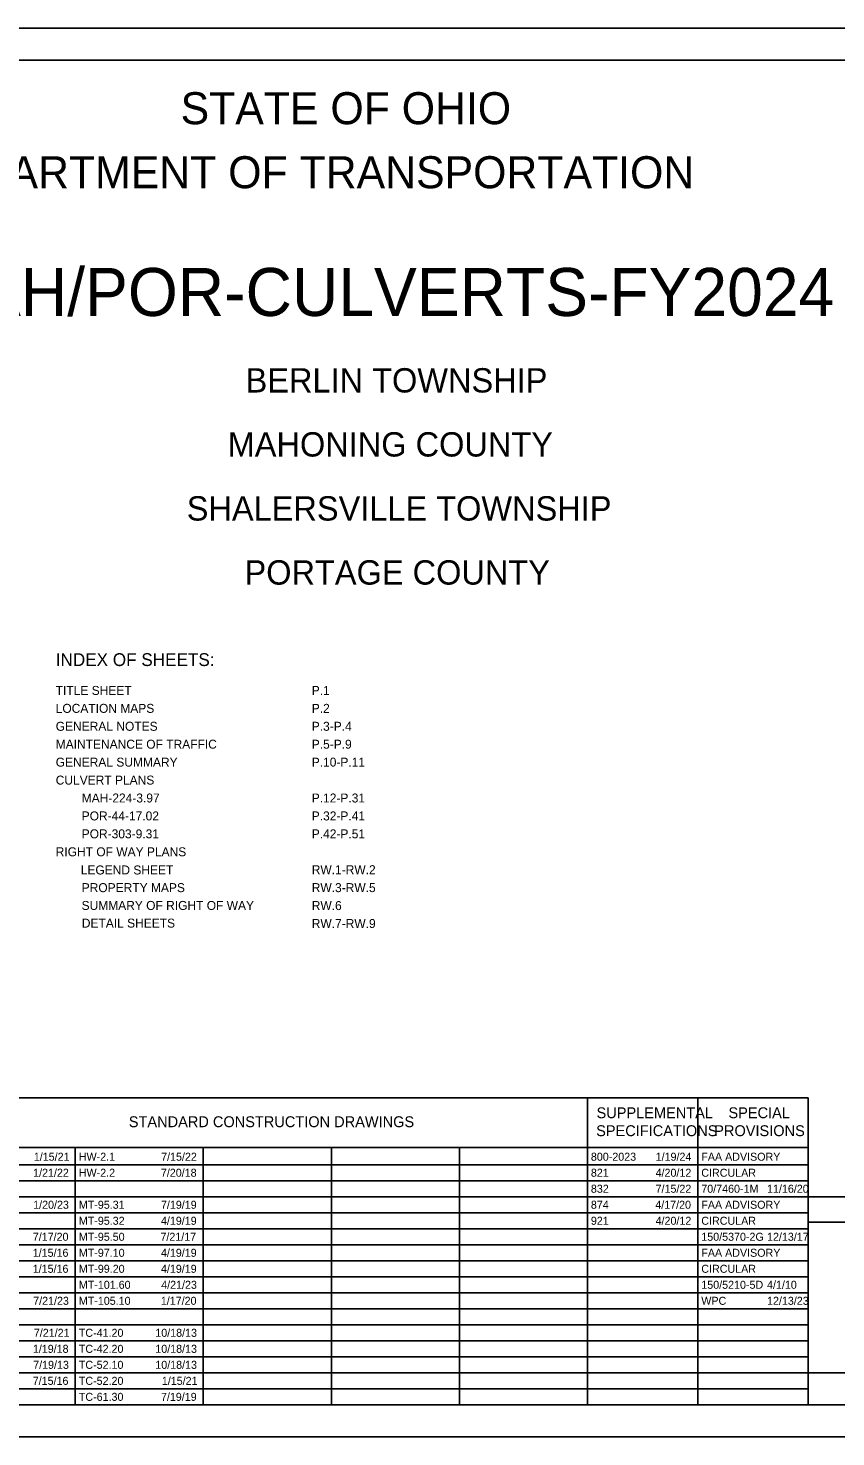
# Model space of a CAD drawing. Extents: x 0 to 34, y 0 to 22.
# Drawn here: x 11.41 to 24.03, y 0 to 22 of the extents above; entities that cross this region are included whole.
import ezdxf

# ---------------------------------------------------------------- set-up
doc = ezdxf.new("R2010")
doc.units = 0
for name, color, linetype in [('SH_Border', 7, 'Continuous'), ('SH_Cut_Line', 7, 'Continuous'), ('SH_Data', 7, 'Continuous'), ('SH_Text', 7, 'Continuous')]:
    doc.layers.add(name, color=color, linetype=linetype)

msp = doc.modelspace()

# ---------------------------------------------------------------- linework, layer by layer
at = {"layer": 'SH_Border'}
msp.add_lwpolyline([(1.5, 21.5), (33.5, 21.5), (33.5, 0.5), (1.5, 0.5)], close=True, dxfattribs=at)
at = {"layer": 'SH_Cut_Line'}
msp.add_lwpolyline([(0, 0), (34, 0), (34, 22), (0, 22)], close=True, dxfattribs=at)
at = {"layer": 'SH_Data'}
for p, q in [((10.15, 5.292), (23.6, 5.292)), ((20.15, 0.5), (20.15, 5.292)), ((21.875, 0.5), (21.875, 5.292)), ((23.6, 0.5), (23.6, 5.292)), ((10.15, 4.521), (23.6, 4.521)), ((12.15, 0.5), (12.15, 4.521)), ((14.15, 0.5), (14.15, 4.521)), ((16.15, 0.5), (16.15, 4.521)), ((18.15, 0.5), (18.15, 4.521)), ((10.15, 4.25), (23.6, 4.25)), ((10.15, 4), (23.6, 4)), ((10.15, 3.75), (23.6, 3.75)), ((23.6, 0.5), (23.6, 3.75)), ((23.6, 0.5), (23.6, 3.75)), ((23.6, 3.75), (26.4, 3.75)), ((10.15, 3.5), (23.6, 3.5)), ((23.6, 3.35), (26.4, 3.35)), ((10.15, 3.25), (23.6, 3.25)), ((10.15, 3), (23.6, 3)), ((10.15, 2.75), (23.6, 2.75)), ((10.15, 2.5), (23.6, 2.5)), ((10.15, 2.25), (23.6, 2.25)), ((10.15, 2), (23.6, 2)), ((10.15, 1.75), (23.6, 1.75)), ((10.15, 1.5), (23.6, 1.5)), ((10.15, 1.25), (23.6, 1.25)), ((10.15, 1), (23.6, 1)), ((10.15, 0.75), (23.6, 0.75)), ((23.6, 0.5), (26.4, 0.5)), ((23.6, 0.5), (26.4, 0.5))]:
    msp.add_line(p, q, dxfattribs=at)
msp.add_lwpolyline([(23.6, 0.5), (23.6, 1), (26.4, 1), (26.4, 0.5)], close=True, dxfattribs=at)

# ---------------------------------------------------------------- texts
at = {"layer": 'SH_Text'}
for s, height, p in [('STATE OF OHIO', 0.5, (13.795, 20.5)), ('DEPARTMENT OF TRANSPORTATION', 0.5, (9.747, 19.5)), ('MAH/POR-CULVERTS-FY2024', 0.75, (9.795, 17.505)), ('   BERLIN TOWNSHIP  ', 0.38, (14.387, 16.31)), ('   MAHONING COUNTY  ', 0.38, (14.107, 15.31)), ('SHALERSVILLE TOWNSHIP', 0.38, (13.891, 14.31)), ('   PORTAGE COUNTY   ', 0.38, (14.37, 13.31)), ('INDEX OF SHEETS:', 0.2, (11.844, 12.038)), ('TITLE SHEET                        ', 0.14, (11.844, 11.587)), ('P.1    ', 0.14, (15.844, 11.587)), ('LOCATION MAPS                      ', 0.14, (11.844, 11.307)), ('P.2    ', 0.14, (15.844, 11.307)), ('GENERAL NOTES                      ', 0.14, (11.844, 11.027)), ('P.3-P.4', 0.14, (15.844, 11.027)), ('MAINTENANCE OF TRAFFIC             ', 0.14, (11.844, 10.747)), ('P.5-P.9', 0.14, (15.844, 10.747)), ('GENERAL SUMMARY                    ', 0.14, (11.844, 10.467)), ('P.10-P.11', 0.14, (15.844, 10.467)), ('CULVERT PLANS                      ', 0.14, (11.844, 10.187)), ('MAH-224-3.97                       ', 0.14, (12.25, 9.907)), ('P.12-P.31', 0.14, (15.844, 9.907)), ('POR-44-17.02                       ', 0.14, (12.25, 9.627)), ('P.32-P.41', 0.14, (15.844, 9.627)), ('POR-303-9.31                       ', 0.14, (12.25, 9.347)), ('P.42-P.51', 0.14, (15.844, 9.347)), ('RIGHT OF WAY PLANS                  ', 0.14, (11.844, 9.067)), ('LEGEND SHEET                        ', 0.14, (12.235, 8.783)), ('RW.1-RW.2 ', 0.14, (15.844, 8.787)), ('PROPERTY MAPS                       ', 0.14, (12.25, 8.507)), ('RW.3-RW.5 ', 0.14, (15.844, 8.507)), ('SUMMARY OF RIGHT OF WAY             ', 0.14, (12.248, 8.229)), ('RW.6      ', 0.14, (15.844, 8.227)), ('DETAIL SHEETS                       ', 0.14, (12.252, 7.953)), ('RW.7-RW.9 ', 0.14, (15.844, 7.947)), ('SUPPLEMENTAL', 0.17, (20.293, 4.976)), ('SPECIAL', 0.17, (22.354, 4.976)), ('STANDARD CONSTRUCTION DRAWINGS', 0.17, (12.986, 4.836)), ('SPECIFICATIONS', 0.17, (20.287, 4.696)), ('PROVISIONS', 0.17, (22.132, 4.696)), ('1/15/21', 0.125, (11.502, 4.312)), ('HW-2.1', 0.125, (12.205, 4.312)), ('7/15/22', 0.125, (13.491, 4.312)), ('800-2023', 0.125, (20.205, 4.312)), ('1/19/24', 0.125, (21.217, 4.312)), ('FAA ADVISORY', 0.125, (21.93, 4.312)), ('1/21/22', 0.125, (11.491, 4.062)), ('HW-2.2', 0.125, (12.205, 4.062)), ('7/20/18', 0.125, (13.487, 4.062)), ('821', 0.125, (20.205, 4.062)), ('4/20/12', 0.125, (21.216, 4.062)), ('CIRCULAR', 0.125, (21.93, 4.062)), ('832', 0.125, (20.205, 3.812)), ('7/15/22', 0.125, (21.216, 3.812)), ('70/7460-1M', 0.125, (21.93, 3.812)), ('11/16/20', 0.125, (22.957, 3.812)), ('1/20/23', 0.125, (11.492, 3.562)), ('MT-95.31', 0.125, (12.205, 3.562)), ('7/19/19', 0.125, (13.488, 3.562)), ('874', 0.125, (20.205, 3.562)), ('4/17/20', 0.125, (21.211, 3.562)), ('FAA ADVISORY', 0.125, (21.93, 3.562)), ('MT-95.32', 0.125, (12.205, 3.312)), ('4/19/19', 0.125, (13.488, 3.312)), ('921', 0.125, (20.205, 3.312)), ('4/20/12', 0.125, (21.216, 3.312)), ('CIRCULAR', 0.125, (21.93, 3.312)), ('7/17/20', 0.125, (11.486, 3.062)), ('MT-95.50', 0.125, (12.205, 3.062)), ('7/21/17', 0.125, (13.48, 3.062)), ('150/5370-2G', 0.125, (21.93, 3.062)), ('12/13/17', 0.125, (22.957, 3.062)), ('1/15/16', 0.125, (11.485, 2.812)), ('MT-97.10', 0.125, (12.205, 2.812)), ('4/19/19', 0.125, (13.488, 2.812)), ('FAA ADVISORY', 0.125, (21.93, 2.812)), ('1/15/16', 0.125, (11.485, 2.562)), ('MT-99.20', 0.125, (12.205, 2.562)), ('4/19/19', 0.125, (13.488, 2.562)), ('CIRCULAR', 0.125, (21.93, 2.562)), ('MT-101.60', 0.125, (12.205, 2.312)), ('4/21/23', 0.125, (13.492, 2.312)), ('150/5210-5D', 0.125, (21.93, 2.312)), ('4/1/10', 0.125, (22.957, 2.312)), ('7/21/23', 0.125, (11.492, 2.062)), ('MT-105.10', 0.125, (12.205, 2.062)), ('1/17/20', 0.125, (13.486, 2.062)), ('WPC', 0.125, (21.93, 2.062)), ('12/13/23', 0.125, (22.957, 2.062)), ('7/21/21', 0.125, (11.502, 1.562)), ('TC-41.20', 0.125, (12.205, 1.562)), ('10/18/13', 0.125, (13.4, 1.562)), ('1/19/18', 0.125, (11.487, 1.312)), ('TC-42.20', 0.125, (12.205, 1.312)), ('10/18/13', 0.125, (13.4, 1.312)), ('7/19/13', 0.125, (11.492, 1.062)), ('TC-52.10', 0.125, (12.205, 1.062)), ('10/18/13', 0.125, (13.4, 1.062)), ('7/15/16', 0.125, (11.485, 0.812)), ('TC-52.20', 0.125, (12.205, 0.812)), ('1/15/21', 0.125, (13.502, 0.812)), ('TC-61.30', 0.125, (12.205, 0.562)), ('7/19/19', 0.125, (13.488, 0.562))]:
    msp.add_text(s, height=height, dxfattribs=at).set_placement(p)

doc.saveas('drawing.dxf')
